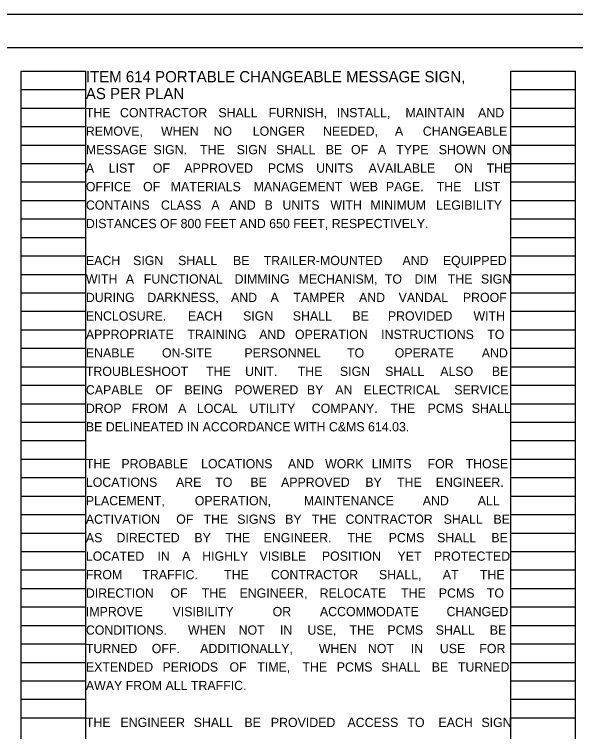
# Model space of a CAD drawing. Extents: x 0 to 34, y 0 to 22.
# Drawn here: x 16.66 to 25.16, y 11.13 to 22 of the extents above; entities that cross this region are included whole.
import ezdxf

# ---------------------------------------------------------------- set-up
doc = ezdxf.new("R2010")
doc.units = 0
for name, color, linetype in [('BD_P_Text', 7, 'Continuous'), ('SH_Border', 7, 'Continuous'), ('SH_Cut_Line', 7, 'Continuous'), ('SH_Data', 7, 'Continuous')]:
    doc.layers.add(name, color=color, linetype=linetype)

msp = doc.modelspace()

# ---------------------------------------------------------------- linework, layer by layer
at = {"layer": 'SH_Border'}
msp.add_lwpolyline([(2, 21.5), (33.5, 21.5), (33.5, 0.5), (2, 0.5)], close=True, dxfattribs=at)
at = {"layer": 'SH_Cut_Line'}
msp.add_lwpolyline([(0, 0), (34, 0), (34, 22), (0, 22)], close=True, dxfattribs=at)
at = {"layer": 'SH_Data'}
for p, q in [((16.76, 0.98), (16.76, 21.14)), ((16.76, 21.14), (17.74, 21.14)), ((17.74, 0.98), (17.74, 21.14)), ((24.18, 0.98), (24.18, 21.14)), ((24.18, 21.14), (25.16, 21.14)), ((25.16, 0.98), (25.16, 21.14)), ((16.76, 20.86), (17.74, 20.86)), ((24.18, 20.86), (25.16, 20.86)), ((16.76, 20.58), (17.74, 20.58)), ((24.18, 20.58), (25.16, 20.58)), ((16.76, 20.3), (17.74, 20.3)), ((24.18, 20.3), (25.16, 20.3)), ((16.76, 20.02), (17.74, 20.02)), ((24.18, 20.02), (25.16, 20.02)), ((16.76, 19.74), (17.74, 19.74)), ((24.18, 19.74), (25.16, 19.74)), ((16.76, 19.46), (17.74, 19.46)), ((24.18, 19.46), (25.16, 19.46)), ((16.76, 19.18), (17.74, 19.18)), ((24.18, 19.18), (25.16, 19.18)), ((16.76, 18.9), (17.74, 18.9)), ((24.18, 18.9), (25.16, 18.9)), ((16.76, 18.62), (17.74, 18.62)), ((24.18, 18.62), (25.16, 18.62)), ((16.76, 18.34), (17.74, 18.34)), ((24.18, 18.34), (25.16, 18.34)), ((16.76, 18.06), (17.74, 18.06)), ((24.18, 18.06), (25.16, 18.06)), ((16.76, 17.78), (17.74, 17.78)), ((24.18, 17.78), (25.16, 17.78)), ((16.76, 17.5), (17.74, 17.5)), ((24.18, 17.5), (25.16, 17.5)), ((16.76, 17.22), (17.74, 17.22)), ((24.18, 17.22), (25.16, 17.22)), ((16.76, 16.94), (17.74, 16.94)), ((24.18, 16.94), (25.16, 16.94)), ((16.76, 16.66), (17.74, 16.66)), ((24.18, 16.66), (25.16, 16.66)), ((16.76, 16.38), (17.74, 16.38)), ((24.18, 16.38), (25.16, 16.38)), ((16.76, 16.1), (17.74, 16.1)), ((24.18, 16.1), (25.16, 16.1)), ((16.76, 15.82), (17.74, 15.82)), ((24.18, 15.82), (25.16, 15.82)), ((16.76, 15.54), (17.74, 15.54)), ((24.18, 15.54), (25.16, 15.54)), ((16.76, 15.26), (17.74, 15.26)), ((24.18, 15.26), (25.16, 15.26)), ((16.76, 14.98), (17.74, 14.98)), ((24.18, 14.98), (25.16, 14.98)), ((16.76, 14.7), (17.74, 14.7)), ((24.18, 14.7), (25.16, 14.7)), ((16.76, 14.42), (17.74, 14.42)), ((24.18, 14.42), (25.16, 14.42)), ((16.76, 14.14), (17.74, 14.14)), ((24.18, 14.14), (25.16, 14.14)), ((16.76, 13.86), (17.74, 13.86)), ((24.18, 13.86), (25.16, 13.86)), ((16.76, 13.58), (17.74, 13.58)), ((24.18, 13.58), (25.16, 13.58)), ((16.76, 13.3), (17.74, 13.3)), ((24.18, 13.3), (25.16, 13.3)), ((16.76, 13.02), (17.74, 13.02)), ((24.18, 13.02), (25.16, 13.02)), ((16.76, 12.74), (17.74, 12.74)), ((24.18, 12.74), (25.16, 12.74)), ((16.76, 12.46), (17.74, 12.46)), ((24.18, 12.46), (25.16, 12.46)), ((16.76, 12.18), (17.74, 12.18)), ((24.18, 12.18), (25.16, 12.18)), ((16.76, 11.9), (17.74, 11.9)), ((24.18, 11.9), (25.16, 11.9)), ((16.76, 11.62), (17.74, 11.62)), ((24.18, 11.62), (25.16, 11.62)), ((16.76, 11.34), (17.74, 11.34)), ((24.18, 11.34), (25.16, 11.34))]:
    msp.add_line(p, q, dxfattribs=at)

# ---------------------------------------------------------------- texts
at = {"layer": 'BD_P_Text'}
for s, height, p in [('ITEM 614 PORTABLE CHANGEABLE MESSAGE SIGN,', 0.17, (17.74, 20.97)), ('AS PER PLAN', 0.17, (17.74, 20.715)), ('THE ', 0.14, (17.74, 20.44)), ('CONTRACTOR ', 0.14, (18.257, 20.44)), ('SHALL ', 0.14, (19.748, 20.44)), ('FURNISH, ', 0.14, (20.509, 20.44)), ('INSTALL, ', 0.14, (21.542, 20.44)), ('MAINTAIN ', 0.14, (22.582, 20.44)), ('AND ', 0.14, (23.682, 20.44)), ('REMOVE, ', 0.14, (17.74, 20.16)), ('WHEN ', 0.14, (18.878, 20.16)), ('NO ', 0.14, (19.674, 20.16)), ('LONGER ', 0.14, (20.268, 20.16)), ('NEEDED, ', 0.14, (21.333, 20.16)), ('A ', 0.14, (22.422, 20.16)), ('CHANGEABLE ', 0.14, (22.845, 20.16)), ('MESSAGE ', 0.14, (17.74, 19.88)), ('SIGN. ', 0.14, (18.764, 19.88)), (' THE ', 0.14, (19.418, 19.88)), ('SIGN ', 0.14, (20.024, 19.88)), ('SHALL ', 0.14, (20.624, 19.88)), ('BE ', 0.14, (21.374, 19.88)), ('OF ', 0.14, (21.757, 19.88)), ('A ', 0.14, (22.165, 19.88)), ('TYPE ', 0.14, (22.442, 19.88)), ('SHOWN ', 0.14, (23.086, 19.88)), ('ON ', 0.14, (23.893, 19.88)), ('A ', 0.14, (17.74, 19.6)), ('LIST ', 0.14, (18.086, 19.6)), ('OF ', 0.14, (18.755, 19.6)), ('APPROVED ', 0.14, (19.232, 19.6)), ('PCMS ', 0.14, (20.498, 19.6)), ('UNITS ', 0.14, (21.229, 19.6)), ('AVAILABLE ', 0.14, (22.023, 19.6)), ('ON ', 0.14, (23.321, 19.6)), ('THE ', 0.14, (23.811, 19.6)), ('OFFICE ', 0.14, (17.74, 19.32)), ('OF ', 0.14, (18.607, 19.32)), ('MATERIALS ', 0.14, (19.026, 19.32)), ('MANAGEMENT ', 0.14, (20.282, 19.32)), ('WEB ', 0.14, (21.74, 19.32)), ('PAGE. ', 0.14, (22.286, 19.32)), (' THE ', 0.14, (23.003, 19.32)), ('LIST ', 0.14, (23.621, 19.32)), ('CONTAINS ', 0.14, (17.74, 19.04)), ('CLASS ', 0.14, (18.877, 19.04)), ('A ', 0.14, (19.641, 19.04)), ('AND ', 0.14, (19.917, 19.04)), ('B ', 0.14, (20.447, 19.04)), ('UNITS ', 0.14, (20.719, 19.04)), ('WITH ', 0.14, (21.444, 19.04)), ('MINIMUM ', 0.14, (22.051, 19.04)), ('LEGIBILITY ', 0.14, (23.046, 19.04)), ('DISTANCES OF 800 FEET AND 650 FEET, RESPECTIVELY.', 0.14, (17.74, 18.76)), ('EACH ', 0.14, (17.74, 18.2)), ('SIGN ', 0.14, (18.456, 18.2)), ('SHALL ', 0.14, (19.137, 18.2)), ('BE ', 0.14, (19.969, 18.2)), ('TRAILER-MOUNTED ', 0.14, (20.434, 18.2)), ('AND ', 0.14, (22.536, 18.2)), ('EQUIPPED ', 0.14, (23.148, 18.2)), ('WITH ', 0.14, (17.74, 17.92)), ('A ', 0.14, (18.345, 17.92)), ('FUNCTIONAL ', 0.14, (18.618, 17.92)), ('DIMMING ', 0.14, (19.994, 17.92)), ('MECHANISM, ', 0.14, (20.962, 17.92)), ('TO ', 0.14, (22.27, 17.92)), ('DIM ', 0.14, (22.719, 17.92)), ('THE ', 0.14, (23.223, 17.92)), ('SIGN ', 0.14, (23.726, 17.92)), ('DURING ', 0.14, (17.74, 17.64)), ('DARKNESS, ', 0.14, (18.671, 17.64)), ('AND ', 0.14, (19.939, 17.64)), ('A ', 0.14, (20.538, 17.64)), ('TAMPER ', 0.14, (20.884, 17.64)), ('AND ', 0.14, (21.878, 17.64)), ('VANDAL ', 0.14, (22.478, 17.64)), ('PROOF ', 0.14, (23.451, 17.64)), ('ENCLOSURE. ', 0.14, (17.74, 17.36)), (' EACH ', 0.14, (19.235, 17.36)), ('SIGN ', 0.14, (20.122, 17.36)), ('SHALL ', 0.14, (20.875, 17.36)), ('PROVIDED ', 0.14, (22.315, 17.36)), ('BE ', 0.14, (21.778, 17.36)), ('WITH ', 0.14, (23.612, 17.36)), ('APPROPRIATE ', 0.14, (17.74, 17.08)), ('TRAINING ', 0.14, (19.279, 17.08)), ('AND ', 0.14, (20.366, 17.08)), ('OPERATION ', 0.14, (20.908, 17.08)), ('INSTRUCTIONS ', 0.14, (22.214, 17.08)), ('TO ', 0.14, (23.821, 17.08)), ('ENABLE ', 0.14, (17.74, 16.8)), ('ON-SITE ', 0.14, (18.893, 16.8)), ('PERSONNEL ', 0.14, (20.142, 16.8)), ('TO ', 0.14, (21.696, 16.8)), ('OPERATE ', 0.14, (22.419, 16.8)), ('AND ', 0.14, (23.738, 16.8)), ('TROUBLESHOOT ', 0.14, (17.74, 16.52)), ('THE ', 0.14, (19.561, 16.52)), ('UNIT. ', 0.14, (20.152, 16.52)), (' THE ', 0.14, (20.897, 16.52)), ('SIGN ', 0.14, (21.589, 16.52)), ('SHALL ', 0.14, (22.274, 16.52)), ('ALSO ', 0.14, (23.109, 16.52)), ('BE ', 0.14, (23.891, 16.52)), ('CAPABLE ', 0.14, (17.74, 16.24)), ('OF ', 0.14, (18.795, 16.24)), ('BEING ', 0.14, (19.234, 16.24)), ('POWERED ', 0.14, (19.992, 16.24)), ('BY ', 0.14, (21.089, 16.24)), ('AN ', 0.14, (21.519, 16.24)), ('ELECTRICAL ', 0.14, (21.949, 16.24)), ('SERVICE ', 0.14, (23.321, 16.24)), ('DROP ', 0.14, (17.74, 15.96)), ('FROM ', 0.14, (18.432, 15.96)), ('A ', 0.14, (19.139, 15.96)), ('LOCAL ', 0.14, (19.423, 15.96)), ('UTILITY ', 0.14, (20.217, 15.96)), ('COMPANY. ', 0.14, (21.162, 15.96)), (' THE ', 0.14, (22.303, 15.96)), ('PCMS ', 0.14, (22.917, 15.96)), ('SHALL ', 0.14, (23.585, 15.96)), ('BE DELINEATED IN ACCORDANCE WITH C&MS 614.03.', 0.14, (17.74, 15.68)), ('THE ', 0.14, (17.74, 15.12)), ('PROBABLE ', 0.14, (18.278, 15.12)), ('LOCATIONS ', 0.14, (19.485, 15.12)), ('AND ', 0.14, (20.801, 15.12)), ('WORK ', 0.14, (21.364, 15.12)), ('LIMITS ', 0.14, (22.072, 15.12)), ('FOR ', 0.14, (22.917, 15.12)), ('THOSE ', 0.14, (23.493, 15.12)), ('LOCATIONS ', 0.14, (17.74, 14.84)), ('ARE ', 0.14, (19.105, 14.84)), ('TO ', 0.14, (19.7, 14.84)), ('BE ', 0.14, (20.232, 14.84)), ('APPROVED ', 0.14, (20.697, 14.84)), ('BY ', 0.14, (21.974, 14.84)), ('THE ', 0.14, (22.454, 14.84)), ('ENGINEER. ', 0.14, (23.04, 14.84)), ('PLACEMENT, ', 0.14, (17.74, 14.56)), ('OPERATION, ', 0.14, (19.39, 14.56)), ('MAINTENANCE ', 0.14, (21.043, 14.56)), ('AND ', 0.14, (22.844, 14.56)), ('ALL ', 0.14, (23.677, 14.56)), ('ACTIVATION ', 0.14, (17.74, 14.28)), ('OF ', 0.14, (19.109, 14.28)), ('THE ', 0.14, (19.522, 14.28)), ('SIGNS ', 0.14, (20.033, 14.28)), ('BY ', 0.14, (20.759, 14.28)), ('THE ', 0.14, (21.163, 14.28)), ('CONTRACTOR ', 0.14, (21.674, 14.28)), ('SHALL ', 0.14, (23.16, 14.28)), ('BE ', 0.14, (23.915, 14.28)), ('AS ', 0.14, (17.74, 14)), ('DIRECTED ', 0.14, (18.204, 14)), ('BY ', 0.14, (19.384, 14)), ('THE ', 0.14, (19.855, 14)), ('ENGINEER. ', 0.14, (20.433, 14)), (' THE ', 0.14, (21.65, 14)), ('PCMS ', 0.14, (22.328, 14)), ('SHALL ', 0.14, (23.061, 14)), ('BE ', 0.14, (23.883, 14)), ('LOCATED ', 0.14, (17.74, 13.72)), ('IN ', 0.14, (18.824, 13.72)), ('A ', 0.14, (19.199, 13.72)), ('HIGHLY ', 0.14, (19.503, 13.72)), ('VISIBLE ', 0.14, (20.37, 13.72)), ('POSITION ', 0.14, (21.315, 13.72)), ('YET ', 0.14, (22.461, 13.72)), ('PROTECTED ', 0.14, (23.013, 13.72)), ('FROM ', 0.14, (17.74, 13.44)), ('TRAFFIC. ', 0.14, (18.595, 13.44)), (' THE ', 0.14, (19.783, 13.44)), ('CONTRACTOR ', 0.14, (20.544, 13.44)), ('SHALL, ', 0.14, (22.18, 13.44)), ('AT ', 0.14, (23.147, 13.44)), ('THE ', 0.14, (23.71, 13.44)), ('DIRECTION ', 0.14, (17.74, 13.16)), ('OF ', 0.14, (19.022, 13.16)), ('THE ', 0.14, (19.496, 13.16)), ('ENGINEER, ', 0.14, (20.068, 13.16)), ('RELOCATE ', 0.14, (21.282, 13.16)), ('THE ', 0.14, (22.515, 13.16)), ('PCMS ', 0.14, (23.087, 13.16)), ('TO ', 0.14, (23.815, 13.16)), ('IMPROVE ', 0.14, (17.74, 12.88)), ('VISIBILITY ', 0.14, (19.053, 12.88)), ('OR ', 0.14, (20.569, 12.88)), ('ACCOMMODATE ', 0.14, (21.286, 12.88)), ('CHANGED ', 0.14, (23.204, 12.88)), ('CONDITIONS. ', 0.14, (17.74, 12.6)), (' WHEN ', 0.14, (19.235, 12.6)), ('NOT ', 0.14, (20.054, 12.6)), ('IN ', 0.14, (20.68, 12.6)), ('USE, ', 0.14, (21.097, 12.6)), ('THE ', 0.14, (21.734, 12.6)), ('PCMS ', 0.14, (22.309, 12.6)), ('SHALL ', 0.14, (23.04, 12.6)), ('BE ', 0.14, (23.859, 12.6)), ('TURNED ', 0.14, (17.74, 12.32)), ('OFF. ', 0.14, (18.738, 12.32)), (' ADDITIONALLY, ', 0.14, (19.42, 12.32)), ('WHEN ', 0.14, (21.269, 12.32)), ('NOT ', 0.14, (22.013, 12.32)), ('IN ', 0.14, (22.662, 12.32)), ('USE ', 0.14, (23.103, 12.32)), ('FOR ', 0.14, (23.701, 12.32)), ('EXTENDED ', 0.14, (17.74, 12.04)), ('PERIODS ', 0.14, (18.901, 12.04)), ('OF ', 0.14, (19.916, 12.04)), ('TIME, ', 0.14, (20.337, 12.04)), ('THE ', 0.14, (21.021, 12.04)), ('PCMS ', 0.14, (21.541, 12.04)), ('SHALL ', 0.14, (22.216, 12.04)), ('BE ', 0.14, (22.98, 12.04)), ('TURNED ', 0.14, (23.377, 12.04)), ('AWAY FROM ALL TRAFFIC.', 0.14, (17.74, 11.76)), ('THE ', 0.14, (17.74, 11.2)), ('ENGINEER ', 0.14, (18.264, 11.2)), ('SHALL ', 0.14, (19.374, 11.2)), ('BE ', 0.14, (20.141, 11.2)), ('PROVIDED ', 0.14, (20.542, 11.2)), ('ACCESS ', 0.14, (21.703, 11.2)), ('TO ', 0.14, (22.612, 11.2)), ('EACH ', 0.14, (23.082, 11.2)), ('SIGN ', 0.14, (23.733, 11.2))]:
    msp.add_text(s, height=height, dxfattribs=at).set_placement(p)

doc.saveas('drawing.dxf')
